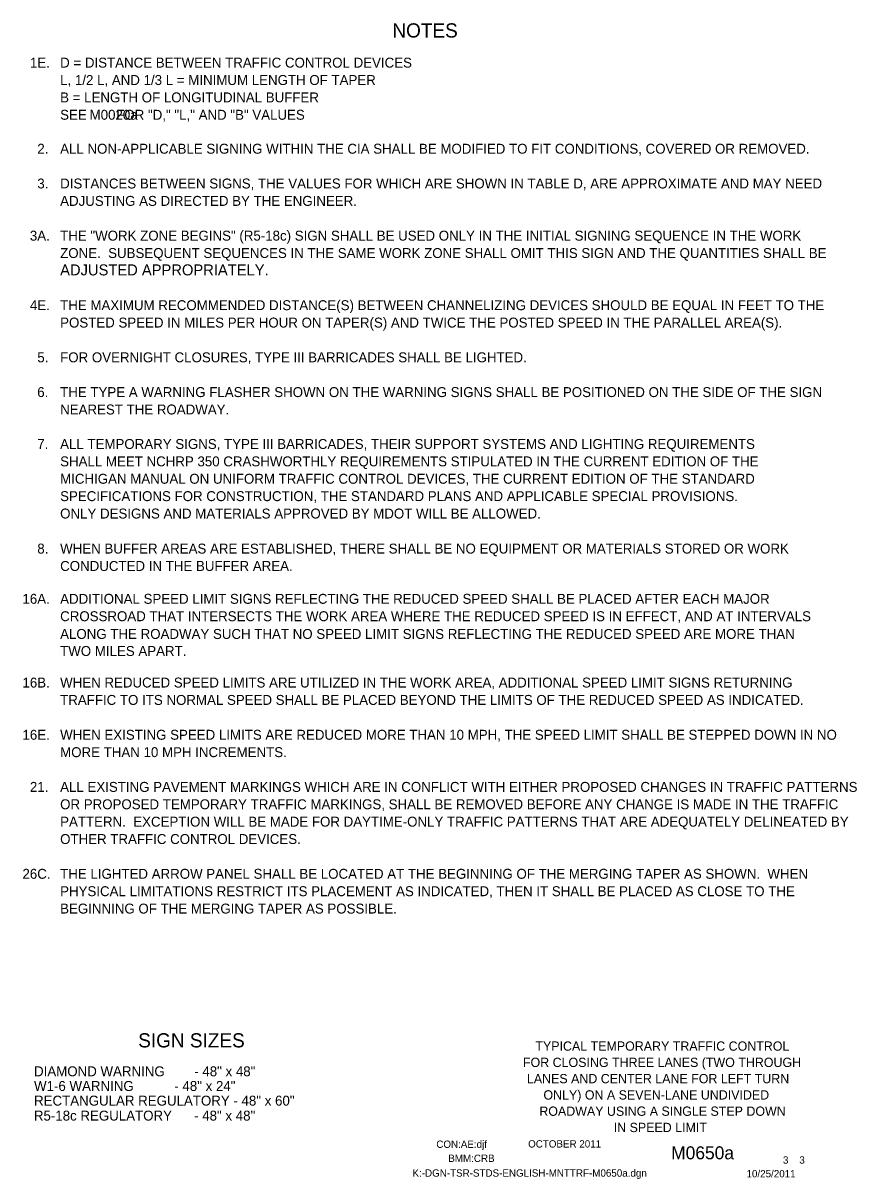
# Model space of a CAD drawing. Extents: x 16544 to 19504, y 5662 to 6909.
# Drawn here: x 18799 to 19504, y 5932 to 6909 of the extents above; entities that cross this region are included whole.
import ezdxf

# ---------------------------------------------------------------- set-up
doc = ezdxf.new("R2010")
doc.units = 0
for name, color, linetype in [('BORDER', 7, 'Continuous'), ('BORDER_SIGNAL_WO', 7, 'Continuous'), ('TYPICAL_TEXT_DIMEN_PR', 7, 'Continuous')]:
    doc.layers.add(name, color=color, linetype=linetype)

msp = doc.modelspace()

# ---------------------------------------------------------------- linework, layer by layer
at = {"layer": 'BORDER'}
msp.add_line((19347.25, 6011.25), (19347.25, 6011.25), dxfattribs=at)
msp.add_line((19347.25, 6011.25), (19347.25, 6011.25), dxfattribs=at)

# ---------------------------------------------------------------- texts
for s, p in [('TYPICAL TEMPORARY TRAFFIC CONTROL', (19232.45, 6040.22)), ('FOR CLOSING THREE LANES (TWO THROUGH', (19221.95, 6026.46)), ('LANES AND CENTER LANE FOR LEFT TURN', (19225.28, 6012.7)), ('ONLY) ON A SEVEN-LANE UNDIVIDED', (19239.26, 5998.93)), ('ROADWAY USING A SINGLE STEP DOWN', (19235.78, 5985.17)), ('IN SPEED LIMIT', (19298.66, 5971.41))]:
    msp.add_text(s, height=7.8528, dxfattribs=at).set_placement(p)
at = {"layer": 'BORDER_SIGNAL_WO'}
for s, height, p in [('CON:AE:djf', 6.2, (19148.69, 5958.06)), ('    OCTOBER 2011    ', 6.2, (19217.08, 5958.34)), ('BMM:CRB   ', 6.2, (19158.81, 5946.17)), ('    M0650a   ', 11, (19330.86, 5948.38)), (' 3    3 ', 6.2, (19439.45, 5944.7)), ('K:-DGN-TSR-STDS-ENGLISH-MNTTRF-M0650a.dgn        ', 6.2, (19128.55, 5933.71)), ('10/25/2011    ', 6.2, (19410.93, 5933.13))]:
    msp.add_text(s, height=height, dxfattribs=at).set_placement(p)
at = {"layer": 'TYPICAL_TEXT_DIMEN_PR'}
for s, height, p in [('NOTES', 12, (19111.55, 6897)), ('1E.', 8.4, (18805.19, 6871.56)), ('D = DISTANCE BETWEEN TRAFFIC CONTROL DEVICES', 8.4, (18830.7, 6871.56)), ('L, 1/2 L, AND 1/3 L = MINIMUM LENGTH OF TAPER', 8.4, (18830.7, 6856.86)), ('B = LENGTH OF LONGITUDINAL BUFFER', 8.4, (18830.7, 6842.16)), ('SEE        FOR "D," "L," AND "B" VALUES', 8.4, (18830.7, 6827.46)), ('M0020a', 8.4, (18855.62, 6827.46)), ('2.', 8.4, (18811.39, 6798.75)), ('ALL NON-APPLICABLE SIGNING WITHIN THE CIA SHALL BE MODIFIED TO FIT CONDITIONS, COVERED OR REMOVED.', 8.4, (18830.7, 6798.75)), ('3.', 8.4, (18811.39, 6769.35)), ('DISTANCES BETWEEN SIGNS, THE VALUES FOR WHICH ARE SHOWN IN TABLE D, ARE APPROXIMATE AND MAY NEED', 8.4, (18830.7, 6769.35)), ('ADJUSTING AS DIRECTED BY THE ENGINEER.', 8.4, (18830.7, 6754.65)), ('THE "WORK ZONE BEGINS" (R5-18c) SIGN SHALL BE USED ONLY IN THE INITIAL SIGNING SEQUENCE IN THE WORK', 8.4, (18830.7, 6725.25)), ('3A.', 8.4, (18805.09, 6725.25)), ('ZONE.  SUBSEQUENT SEQUENCES IN THE SAME WORK ZONE SHALL OMIT THIS SIGN AND THE QUANTITIES SHALL BE', 8.4, (18830.7, 6710.55)), ('ADJUSTED APPROPRIATELY.', 9.3, (18830.7, 6695.85)), ('THE MAXIMUM RECOMMENDED DISTANCE(S) BETWEEN CHANNELIZING DEVICES SHOULD BE EQUAL IN FEET TO THE', 8.4, (18830.7, 6666.45)), ('4E.', 8.4, (18805.13, 6666.45)), ('POSTED SPEED IN MILES PER HOUR ON TAPER(S) AND TWICE THE POSTED SPEED IN THE PARALLEL AREA(S).', 8.4, (18830.7, 6651.75)), ('5.', 8.4, (18811.39, 6622.35)), ('FOR OVERNIGHT CLOSURES, TYPE III BARRICADES SHALL BE LIGHTED.', 8.4, (18830.7, 6622.35)), ('6.', 8.4, (18811.34, 6592.95)), ('THE TYPE A WARNING FLASHER SHOWN ON THE WARNING SIGNS SHALL BE POSITIONED ON THE SIDE OF THE SIGN', 8.4, (18830.7, 6592.95)), ('NEAREST THE ROADWAY.', 8.4, (18830.7, 6578.25)), ('7.', 8.4, (18811.34, 6549.05)), ('ALL TEMPORARY SIGNS, TYPE III BARRICADES, THEIR SUPPORT SYSTEMS AND LIGHTING REQUIREMENTS', 8.4, (18830.69, 6549.07)), ('SHALL MEET NCHRP 350 CRASHWORTHLY REQUIREMENTS STIPULATED IN THE CURRENT EDITION OF THE', 8.4, (18830.69, 6534.37)), ('MICHIGAN MANUAL ON UNIFORM TRAFFIC CONTROL DEVICES, THE CURRENT EDITION OF THE STANDARD', 8.4, (18830.69, 6519.67)), ('SPECIFICATIONS FOR CONSTRUCTION, THE STANDARD PLANS AND APPLICABLE SPECIAL PROVISIONS.', 8.4, (18830.69, 6504.97)), ('ONLY DESIGNS AND MATERIALS APPROVED BY MDOT WILL BE ALLOWED.', 8.4, (18830.69, 6490.27)), ('8.', 8.4, (18811.39, 6460.63)), ('WHEN BUFFER AREAS ARE ESTABLISHED, THERE SHALL BE NO EQUIPMENT OR MATERIALS STORED OR WORK     ', 8.4, (18830.7, 6460.63)), ('CONDUCTED IN THE BUFFER AREA.', 8.4, (18830.7, 6445.93)), ('16A.', 8.4, (18798.83, 6418.14)), ('ADDITIONAL SPEED LIMIT SIGNS REFLECTING THE REDUCED SPEED SHALL BE PLACED AFTER EACH MAJOR', 8.4, (18830.7, 6418.14)), ('CROSSROAD THAT INTERSECTS THE WORK AREA WHERE THE REDUCED SPEED IS IN EFFECT, AND AT INTERVALS', 8.4, (18830.7, 6403.44)), ('ALONG THE ROADWAY SUCH THAT NO SPEED LIMIT SIGNS REFLECTING THE REDUCED SPEED ARE MORE THAN', 8.4, (18830.7, 6388.44)), ('TWO MILES APART.', 8.4, (18830.7, 6374.04)), ('16B.', 8.4, (18798.84, 6347.31)), ('WHEN REDUCED SPEED LIMITS ARE UTILIZED IN THE WORK AREA, ADDITIONAL SPEED LIMIT SIGNS RETURNING', 8.4, (18830.7, 6347.36)), ('TRAFFIC TO ITS NORMAL SPEED SHALL BE PLACED BEYOND THE LIMITS OF THE REDUCED SPEED AS INDICATED.', 8.4, (18830.7, 6332.66)), ('16E.', 8.4, (18798.84, 6303.18)), ('WHEN EXISTING SPEED LIMITS ARE REDUCED MORE THAN 10 MPH, THE SPEED LIMIT SHALL BE STEPPED DOWN IN NO', 8.4, (18830.7, 6303.18)), ('MORE THAN 10 MPH INCREMENTS.', 8.4, (18830.7, 6288.48)), ('21.', 8.4, (18805.14, 6259.11)), ('ALL EXISTING PAVEMENT MARKINGS WHICH ARE IN CONFLICT WITH EITHER PROPOSED CHANGES IN TRAFFIC PATTERNS', 8.4, (18830.7, 6259.11)), ('OR PROPOSED TEMPORARY TRAFFIC MARKINGS, SHALL BE REMOVED BEFORE ANY CHANGE IS MADE IN THE TRAFFIC', 8.4, (18830.7, 6244.41)), ('PATTERN.  EXCEPTION WILL BE MADE FOR DAYTIME-ONLY TRAFFIC PATTERNS THAT ARE ADEQUATELY DELINEATED BY', 8.4, (18830.7, 6229.71)), ('OTHER TRAFFIC CONTROL DEVICES.', 8.4, (18830.7, 6215.01)), ('26C.', 8.4, (18798.83, 6185.61)), ('THE LIGHTED ARROW PANEL SHALL BE LOCATED AT THE BEGINNING OF THE MERGING TAPER AS SHOWN.  WHEN', 8.4, (18830.7, 6185.61)), ('PHYSICAL LIMITATIONS RESTRICT ITS PLACEMENT AS INDICATED, THEN IT SHALL BE PLACED AS CLOSE TO THE', 8.4, (18830.7, 6170.91)), ('BEGINNING OF THE MERGING TAPER AS POSSIBLE.', 8.4, (18830.7, 6156.21)), ('SIGN SIZES', 12, (18896.69, 6043)), ('DIAMOND WARNING        - 48" x 48"', 8.4, (18808.65, 6018.6)), ('W1-6 WARNING           - 48" x 24"', 8.4, (18808.65, 6006.2)), ('RECTANGULAR REGULATORY - 48" x 60"', 8.4, (18808.65, 5993.8)), ('R5-18c REGULATORY      - 48" x 48"', 8.4, (18808.5, 5981.14))]:
    msp.add_text(s, height=height, dxfattribs=at).set_placement(p)

doc.saveas('drawing.dxf')
